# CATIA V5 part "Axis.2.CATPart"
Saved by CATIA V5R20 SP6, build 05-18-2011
Part number: Axis.2
Publications: "Point.2", "Line.5", "Line.6", "Line.4"
Bounding box of the stored display mesh (mm): x -20 to 20, y -70 to -30, z 11.09 to 48.91
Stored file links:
  C:\Work\#01 CATIA Lecture Materials\#299 TOYOTA CATIA V5\TOYOTA_CATIA\LCS\Surface\Surface EX03\Axis.2.CATPart
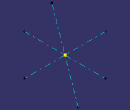
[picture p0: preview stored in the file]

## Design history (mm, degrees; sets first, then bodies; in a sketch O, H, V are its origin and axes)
Set1 "Axis"
  Point1 "Point.2": stored without definition
  Line1 "Line.5": stored without definition
  Line2 "Line.6": stored without definition
  Line3: stored without definition
Body1 (main body)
